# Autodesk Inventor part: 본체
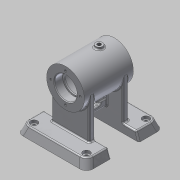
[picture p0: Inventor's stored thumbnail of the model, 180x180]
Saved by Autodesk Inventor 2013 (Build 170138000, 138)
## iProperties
Created: 2016-07
Part Number: 본체
Material: 알루미늄 6061
Document SubType Name: Modeling
Designer: Administrator
Density: 2.71 g/cm^3
Mass: 500.66 g
Surface Area: 530.533 cm^2
Volume: 184.745 cm^3
Author: Administrator
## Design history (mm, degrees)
sketch "스케치2"
  geometry: L1 (0, 0)-(70, 0); L2 (0, 27)-(70, 27); L3 (0, 27)-(0, 16); L4 (0, 16)-(12, 16); L5 (12, 16)-(12, 14); L6 (12, 14)-(14, 14); L7 (14, 14)-(14, 22); L8 (14, 22)-(56, 22); L9 (56, 22)-(56, 14); L10 (56, 14)-(58, 14); L11 (58, 14)-(58, 16); L12 (58, 16)-(70, 16); L13 (70, 16)-(70, 27)
  constraints: 26 end point, 6 parallel, 6 perpendicular, 1 horizontal, 1 vertical
  dimensions: "d0" = 0 distance from line of L3 L1.start; "d1" = 32 diameter of L4 L1; "d2" = 12 distance between parallel lines of L5 L3; "d3" = 54 diameter of L2 L1; "d4" = 28 diameter of L6 L1; "d5" = 42 distance between parallel lines of L9 L7; "d6" = 44 diameter of L8 L1; "d7" = 2 distance of L5.end L6.end; "d8" = 70 distance of L2.start L2.end; "d9" = 32 diameter of L12 L1; "d10" = 2 distance of L9.end L10.end; "d11" = 28 diameter of L10 L1
revolve "회전1" sketch "스케치2" stored, may be unused: angle "d12" = 90 deg
node "작업 평면1"
sketch "스케치3"
  geometry: L1 (27, 70)-(-27, 70) reference; L2 (27, 0)-(-27, 0) reference; L3 (27, 0)-(-27, 0) reference; L4 (-25.21, 35)-(27.411, 35); L5 (-50, 90)-(50, 90); L6 (50, 90)-(50, 55); L7 (50, 55)-(-50, 55); L8 (-50, 55)-(-50, 90); L9 (0, 70)-(0, 0); L10 (-50, 15)-(50, 15); L11 (50, 15)-(50, -20); L12 (50, -20)-(-50, -20); L13 (-50, -20)-(-50, 15); L14 (-4, 55)-(-4, 15); L15 (4, 15)-(4, 55)
  constraints: 24 end point, 6 parallel, 4 perpendicular, 4 point on line, 2 horizontal, 1 midpoint
  dimensions: "d14" = 35 distance between parallel lines of L4 L1; "d16" = 100 distance between parallel lines of L6 L8; "d18" = 50 distance between parallel lines of L9 L8; "d19" = 35 distance between parallel lines of L5 L7; "d20" = 55 distance between parallel lines of L4 L5; "d21" = 55 distance between parallel lines of L12 L4; "d22" = 35 distance between parallel lines of L12 L10; "d23" = 100 distance between parallel lines of L13 L11; "d24" = 50 distance between parallel lines of L9 L13; "d25" = 8 distance between parallel lines of L15 L14; "d26" = 4 distance between parallel lines of L9 L14 (= 0.5 x d25)
extrude "돌출1" join sketch "스케치3" distance "d27" = 12; taper "d28" = 0 deg
sketch "스케치4"
  geometry: L1 (0, 0)-(100, 0) reference; L2 (100, 0)-(100, 12) reference; L3 (0, 12)-(100, 12) reference; L4 (0, 0)-(0, 12) reference; L5 (95.632, 12)-(100, 0); L6 (4.368, 12)-(0, 0); 1 further point
  constraints: 4 end point, 2 point on line
  dimensions: "d29" = 110 deg angle of L1 L5; "d30" = 110 deg angle of L1 L6
extrude "돌출2" cut sketch "스케치4" stored distance "d31" = 12; taper "d32" = 0 deg
node "작업 평면2"
sketch "스케치5"
  geometry: L1 (15, -58)-(15, -70) reference; L2 (-20, -58)-(15, -58) reference; L3 (-20, -70)-(-20, -58) reference; L4 (-20, -70)-(15, -70) reference; L5 (55, -70)-(55, -58) reference; L6 (55, -70)-(90, -70) reference; L7 (90, -58)-(90, -70) reference; L8 (55, -58)-(90, -58) reference; L9 (-20, -70)-(-15.632, -58); L10 (90, -70)-(85.632, -58); 1 further point
  constraints: 4 end point, 2 point on line
  dimensions: "d34" = 110 deg angle of L4 L9; "d35" = 110 deg angle of L6 L10
extrude "돌출3" cut sketch "스케치5" stored distance "d36" = 12; taper "d37" = 0 deg
sketch "스케치6"
  geometry: L1 (45.632, 15)-(4, 15) reference; L2 (4, 55)-(45.632, 55) reference; L3 (-45.632, 55)-(-4, 55) reference; L4 (-4, 55)-(-4, 15) reference; L5 (-4, 15)-(-45.632, 15) reference; L6 (27, 15)-(27, 7); L7 (27, 7)-(-27, 7); L8 (-27, 7)-(-27, 15); L9 (27, 55)-(27, 63); L10 (27, 63)-(-27, 63); L11 (-27, 63)-(-27, 55); L12 (0, 15)-(0, 55); L13 (-4, 15)-(-4, 55); L14 (4, 55)-(4, 15); L15 (-27, 15)-(-4, 15); L16 (4, 15)-(27, 15); L17 (4, 55)-(27, 55); L18 (-4, 55)-(-27, 55); 1 further point
  constraints: 26 end point, 5 collinear, 2 parallel, 2 point on line, 1 perpendicular
  dimensions: "d42" = 54 distance between parallel lines of L6 L8; "d48" = 54 distance between parallel lines of L9 L11; "d49" = 4 distance between parallel lines of L12 L4; "d50" = 27 distance from line of point (0, 0) L8; "d51" = 27 distance between parallel lines of L12 L11; "d52" = 8 distance between parallel lines of L2 L10; "d54" = 8 distance between parallel lines of L15 L7; "d55" = 8 distance of L6.start L6.end; "d56" = 0 distance from line of L15 L12.start; "d57" = 0 distance from line of L12.end L3
extrude "돌출4" join sketch "스케치6" stored distance "d58" = 12; taper "d59" = 0 deg
sketch "스케치7"
  geometry: L1 (0, 0)-(0, 40) reference; L2 (-22.298, 0)-(-22.298, 40); L3 (-43.298, 0)-(-43.298, 40) reference; L4 (-22.298, 0)-(0, 0); L5 (0, 40)-(-22.298, 40); L6 (0, 40)-(0, 0); 1 further point
  constraints: 8 end point, 2 equal length, 1 perpendicular
  dimensions: "d62" = 21 distance between parallel lines of L2 L3
extrude "돌출5" cut sketch "스케치7" stored distance "d63" = 12; taper "d64" = 0 deg
sketch "스케치8"
  geometry: L1 (21, 0)-(21, 40) reference; L2 (0, 0)-(0, 40) reference; L3 (21, 0)-(0, 0) reference; L4 (11.298, 8.5)-(11.298, 31.5); L5 (43.298, 40)-(43.298, 75) reference; L6 (0, 20)-(21, 20); L7 (0.298, -15)-(-53.702, -15) reference; L8 (7.798, 12)-(7.798, 28); L9 (14.798, 12)-(14.798, 28); A1 r 3.5 centre (11.298, 12) between (7.798, 12) and (14.798, 12); A2 r 3.5 centre (11.298, 28) between (14.798, 28) and (7.798, 28); 1 further point
  constraints: 8 end point, 4 point on circle, 4 tangent, 2 centre point, 2 midpoint, 2 perpendicular, 2 point on line
  dimensions: "d65" = 7 diameter of A1; "d67" = 7 diameter of A2; "d69" = 32 distance between parallel lines of L5 L4; "d70" = 35 distance between parallel lines of L6 L7; "d71" = 23 distance of L4.start L4.end; "d72" = 11.5 distance from line of L6 L4.start (= 0.5 x d71); "d73" = 23 dimension on A2 A1; "d74" = 11.5 dimension on A1 L6
extrude "돌출6" cut sketch "스케치8" stored distance "d75" = 12; taper "d76" = 0 deg
node "작업 평면3"
sketch "스케치9"
  geometry: L1 (0, 0)-(15.898, -25.441); L2 (0, 0)-(0, -14)
  constraints: 4 end point, 1 vertical, 1 vertical alignment, 1 other
  dimensions: "d78" = 30 distance of L1.start L1.end; "d79" = 32 deg angle of L2 L1
node "작업 평면4"
sketch "스케치10"
  geometry: L1 (-8, -14.89)-(8, -14.89) reference; L2 (-20, 7.963)-(-20, -7.838) reference; C1 r 6 at (0, 0.063); 3 further points
  constraints: 2 midpoint, 1 centre point, 1 horizontal alignment, 1 vertical alignment
  dimensions: "d80" = 12 diameter of C1
extrude "돌출7" join sketch "스케치10" stored distance "d82" = 12; taper "d83" = 0 deg
node "작업 평면6"
sketch "스케치11"
  geometry: L1 (27, 70)-(-27, 70) reference; C1 r 5 at (0, 48); 1 further point
  constraints: 1 centre point, 1 vertical alignment
  dimensions: "d85" = 10 diameter of C1; "d87" = 22 distance from line of L1 C1.centre
extrude "돌출8" join sketch "스케치11" stored distance "d88" = 12; taper "d89" = 0 deg
sketch "스케치12"
  geometry: L1 (-27, 55)-(-27, 63) reference; L2 (-27, 63)-(27, 63) reference; L3 (27, 63)-(27, 55) reference; L4 (27, 55)-(45.632, 55) reference; L5 (45.632, 55)-(45.632, 85.632) reference; L6 (45.632, 85.632)-(-45.632, 85.632) reference; L7 (-45.632, 85.632)-(-45.632, 55) reference; L8 (-45.632, 55)-(-27, 55) reference; L9 (-50, 15)-(-50, -20) reference; L10 (-50, -20)-(50, -20) reference; C1 r 5 at (-37.5, -7.5); 1 further point
  constraints: 1 centre point
  dimensions: "d90" = 10 diameter of C1; "d92" = 12.5 distance from line of L9 C1.centre; "d93" = 12.5 distance from line of L10 C1.centre
extrude "돌출9" cut sketch "스케치12" distance "d94" = 4; taper "d95" = 0 deg
sketch "스케치13"
  geometry: C1 r 5 at (0, 0) reference; C2 r 3 at (0, 0); 1 further point
  constraints: 1 centre point, 1 coincident
  dimensions: "d96" = 6 diameter of C2
extrude "돌출10" cut sketch "스케치13" stored distance "d98" = 4; taper "d99" = 0 deg
fillet "모깎기1" dims "d106" = 10
fillet "모깎기2" dims "d107" = 2
fillet "모깎기3" dims "d108" = 2
fillet "모깎기4" dims "d109" = 2
chamfer "모따기1" distance "d110" = 1; stored, may be unused: second distance "d111" = 2, angle "d112" = 110 deg
fillet "모깎기5" dims "d113" = 0.3
fillet "모깎기6" dims "d114" = 3
fillet "모깎기7" dims "d115" = 2
fillet "모깎기8" dims "d116" = 2
fillet "모깎기9" dims "d117" = 2
fillet "모깎기10" dims "d118" = 2
fillet "모깎기11" dims "d119" = 2
sketch "스케치14"
  geometry: C1 r 6 at (0, 0) reference; C2 r 3 at (0, 0); 1 further point
  constraints: 1 centre point, 1 coincident
  dimensions: "d120" = 6 diameter of C2
hole "구멍1" sketch "스케치14" at (0, 0) diameter "d122" = 5.188; stored, may be unused: countersink angle "d126" = 90 deg, drill point angle "d128" = 118 deg; dims "d123" = 6, "d124" = 4, "d125" = 2, "d127" = 8
sketch "스케치15"
  geometry: C1 r 5 at (0, 0) reference; C2 r 3 at (0, 0); 1 further point
  constraints: 1 centre point, 1 coincident
  dimensions: "d129" = 6 diameter of C2
hole "구멍2" sketch "스케치15" at (0, 0) diameter "d131" = 5.188; stored, may be unused: countersink angle "d135" = 90 deg, drill point angle "d137" = 118 deg; dims "d132" = 6, "d133" = 4, "d134" = 2, "d136" = 8
node "작업 평면7"
sketch "스케치16"
  geometry: L1 (-20.739, 1.26)-(20.739, 1.26); L2 (20.739, 1.26)-(20.739, -1.26); L3 (20.739, -1.26)-(-20.739, -1.26); L4 (-20.739, -1.26)-(-20.739, 1.26); L5 (-20.739, 0)-(20.739, 0); L6 (0, 1.26)-(0, -1.26); L7 (8, -32.5)-(-8, -32.5) reference; 3 further points
  constraints: 6 midpoint, 4 end point, 1 horizontal, 1 vertical alignment, 2 other
  dimensions: "d138" = 0 distance from line of point (35, 0) L5
feature "엠보싱1" sketch "스케치16" dims "d4" = 28, "d139" = 0.5, "d140" = 0
sketch "스케치17" dims "d141" = 42
  geometry: C1 r 27 at (0, 0) reference; C2 r 17 at (0, 0) reference; C3 r 2 at (0, 21); 1 further point
  constraints: 2 vertical alignment, 1 centre point, 1 coincident, 2 other
  dimensions: "d143" = 4 diameter of C3
hole "구멍3" sketch "스케치17" at (0, 21) diameter "d144" = 3.242; stored, may be unused: countersink angle "d148" = 82 deg, drill point angle "d150" = 118 deg; dims "d145" = 8, "d146" = 3.023, "d147" = 2, "d149" = 10
sketch "스케치18" dims "d154" = 42
  geometry: C1 r 27 at (0, 0) reference; C2 r 17 at (0, 0) reference; C3 r 2 at (0, -21); 1 further point
  constraints: 2 vertical alignment, 1 centre point, 1 coincident, 2 other
  dimensions: "d156" = 4 diameter of C3
hole "구멍4" sketch "스케치18" at (0, -21) diameter "d157" = 3.242; stored, may be unused: countersink angle "d161" = 82 deg, drill point angle "d163" = 118 deg; dims "d158" = 8, "d159" = 3.023, "d160" = 2, "d162" = 10
fillet "모깎기12" dims "d167" = 2
node "솔리드1"
pattern_linear "직사각형 패턴1" dims "d102" = 85, "d105" = 75
pattern_circular "원형 패턴1" dims angle "d152" = 360 deg
pattern_circular "원형 패턴2" dims angle "d165" = 360 deg
node "투영된 루프1"
node "투영된 루프2"
node "투영된 루프3"
node "투영된 루프4"
other parameters: "d77" = 35
